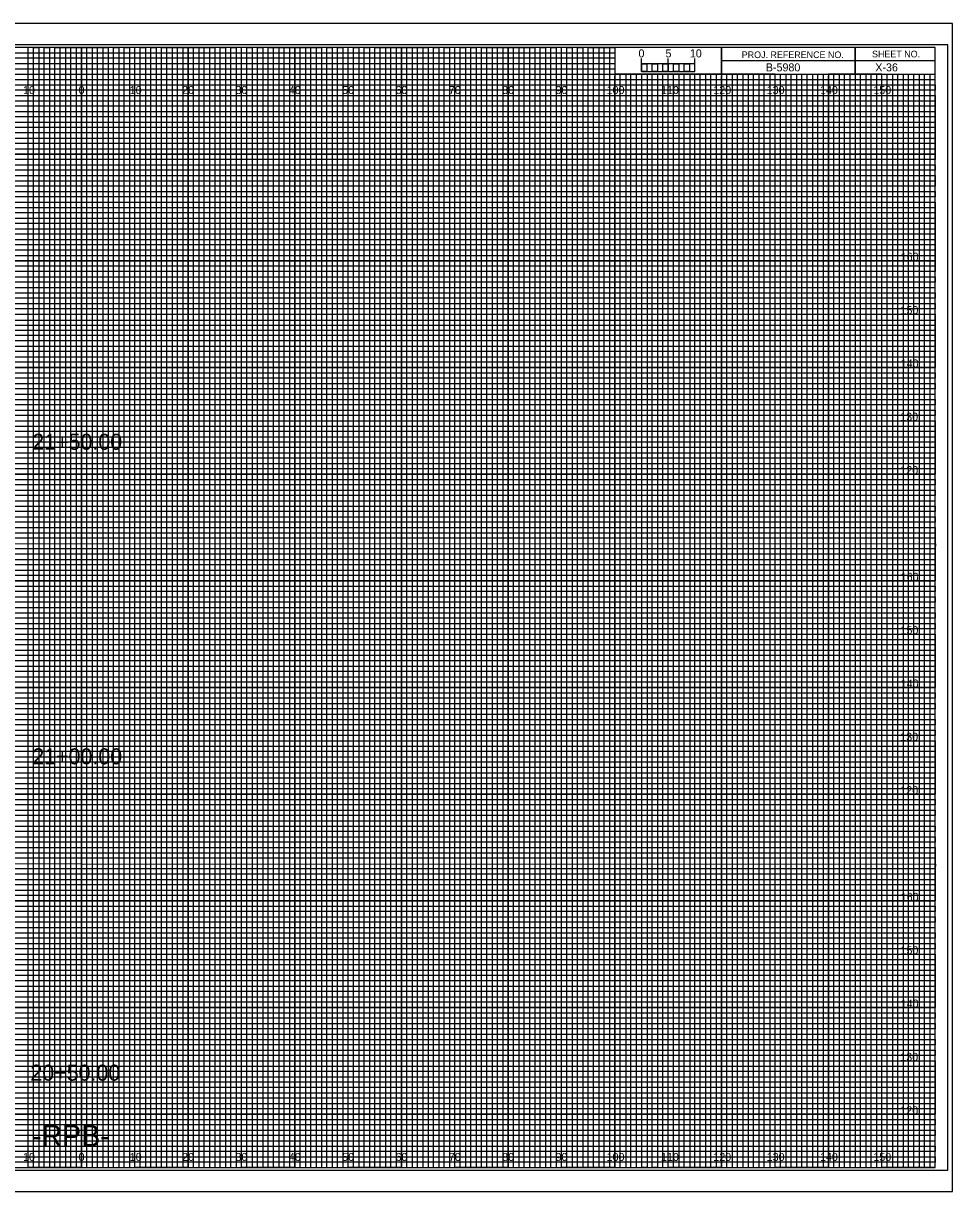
# Model space of a CAD drawing. Extents: x -13 to 323, y -5 to 1094.
# Drawn here: x 149.1 to 323.3, y 655.5 to 874.5 of the extents above; entities that cross this region are included whole.
import ezdxf

# ---------------------------------------------------------------- set-up
doc = ezdxf.new("R2010")
doc.units = 0
for name, color, linetype in [('Exist Cross Section Cell', 7, 'Continuous'), ('Exist XS Center Line Elevation Label', 7, 'Continuous'), ('Exist XS Ground Line', 7, 'Continuous'), ('Prop CMT Concrete Structures', 7, 'Continuous'), ('Prop CMT Guardrail Graphics', 7, 'Continuous'), ('Prop CMT Pvmt Course 1', 7, 'Continuous'), ('Prop CMT Pvmt Course 1 CG', 7, 'Continuous'), ('Prop CMT Pvmt Course 2', 7, 'Continuous'), ('Prop CMT Pvmt Course 3', 7, 'Continuous'), ('Prop CMT Pvmt Surface', 7, 'Continuous'), ('Prop CMT Pvmt Surface Shoulder', 7, 'Continuous'), ('Prop CMT Shld Paved Course 1', 7, 'Continuous'), ('Prop CMT Shld Paved Course 2', 7, 'Continuous'), ('Prop CMT Shld Paved Course 3', 7, 'Continuous'), ('Prop CMT Slope Grass', 7, 'Continuous'), ('Prop CMT Subgrade Earthwork', 7, 'Continuous'), ('Scratch_Level_1', 7, 'Continuous')]:
    doc.layers.add(name, color=color, linetype=linetype)

msp = doc.modelspace()

# ---------------------------------------------------------------- linework, layer by layer
at = {"layer": 'Exist XS Center Line Elevation Label'}
for points in [[(145, 660), (155, 660), (155, 870), (165, 870), (165, 660), (175, 660), (175, 870), (185, 870), (185, 660), (195, 660), (195, 870), (205, 870), (205, 660), (215, 660), (215, 870), (225, 870), (225, 660), (235, 660), (235, 870), (245, 870), (245, 660), (255, 660), (255, 870), (259.93, 870), (260, 870), (260, 865), (264.99, 865), (264.99, 660), (275, 660), (275, 865), (285, 865), (285, 660), (295, 660), (295, 865), (305, 865), (305, 660), (315, 660), (315, 865)], [(0, 865), (275, 865)], [(0, 845), (320, 845), (320, 855), (0, 855)], [(0, 825), (320, 825), (320, 835), (0, 835)], [(0, 805), (320, 805), (320, 815), (0, 815)], [(0, 785), (320, 785), (320, 795), (0, 795)], [(0, 765), (320, 765), (320, 775), (0, 775)], [(0, 745), (320, 745), (320, 755), (0, 755)], [(0, 725), (320, 725), (320, 735), (0, 735)], [(0, 705), (320, 705), (320, 715), (0, 715)], [(0, 685), (320, 685), (320, 695), (0, 695)], [(0, 665), (320, 665), (320, 675), (0, 675)]]:
    msp.add_lwpolyline(points, dxfattribs=at)
at = {"layer": 'Exist XS Ground Line'}
for p, q in [((150, 870), (140, 870)), ((150, 660), (150, 870)), ((170, 870), (160, 870)), ((160, 870), (160, 660)), ((170, 660), (170, 870)), ((190, 870), (180, 870)), ((180, 870), (180, 660)), ((190, 660), (190, 870)), ((210, 870), (200, 870)), ((200, 870), (200, 660)), ((210, 660), (210, 870)), ((230, 870), (220, 870)), ((220, 870), (220, 660)), ((230, 660), (230, 870)), ((250, 870), (240, 870)), ((240, 870), (240, 660)), ((250, 660), (250, 870)), ((260, 870), (260, 660)), ((270, 660), (270, 865)), ((290, 865), (280, 865)), ((280, 865), (280, 660)), ((290, 660), (290, 865)), ((310, 865), (300, 865)), ((300, 865), (300, 660)), ((310, 660), (310, 865)), ((160, 660), (150, 660)), ((180, 660), (170, 660)), ((200, 660), (190, 660)), ((220, 660), (210, 660)), ((240, 660), (230, 660)), ((260, 660), (250, 660)), ((280, 660), (270, 660)), ((300, 660), (290, 660)), ((320, 660), (310, 660)), ((320, 660), (320, 660))]:
    msp.add_line(p, q, dxfattribs=at)
for points in [[(0, 860), (320, 860), (320, 850), (0, 850)], [(0, 840), (320, 840), (320, 830), (0, 830)], [(0, 820), (320, 820), (320, 810), (0, 810)], [(0, 800), (320, 800), (320, 790), (0, 790)], [(0, 780), (320, 780), (320, 770), (0, 770)], [(0, 760), (320, 760), (320, 750), (0, 750)], [(0, 740), (320, 740), (320, 730), (0, 730)], [(0, 720), (320, 720), (320, 710), (0, 710)], [(0, 700), (320, 700), (320, 690), (0, 690)], [(0, 680), (320, 680), (320, 670), (0, 670)]]:
    msp.add_lwpolyline(points, dxfattribs=at)
at = {"layer": 'Prop CMT Pvmt Course 2'}
for p, q in [((265, 865.49), (265, 867.9)), ((265, 866.9), (265, 867.9)), ((270, 865.49), (270, 867.9)), ((275, 865.49), (275, 867.9)), ((275, 866.9), (275, 867.9))]:
    msp.add_line(p, q, dxfattribs=at)
for points in [[(275, 866.9), (265, 866.9), (265, 865.49), (275, 865.49)], [(265, 866.9), (266, 866.9), (266, 865.49), (265, 865.49)], [(267, 866.9), (268, 866.9), (268, 865.49), (267, 865.49)], [(269, 866.9), (270, 866.9), (270, 865.49), (269, 865.49)], [(271, 866.9), (272, 866.9), (272, 865.49), (271, 865.49)], [(273, 866.9), (274, 866.9), (274, 865.49), (273, 865.49)]]:
    msp.add_lwpolyline(points, close=True, dxfattribs=at)
at = {"layer": 'Prop CMT Pvmt Course 3'}
msp.add_lwpolyline([(-13.4, 655.5), (323.3, 655.5), (323.3, 874.5), (-13.4, 874.5)], close=True, dxfattribs=at)
at = {"layer": 'Prop CMT Pvmt Surface'}
for p, q in [((150, 660), (150, 870)), ((160, 660), (160, 870)), ((170, 660), (170, 870)), ((180, 660), (180, 870)), ((190, 660), (190, 870)), ((200, 660), (200, 870)), ((210, 660), (210, 870)), ((220, 660), (220, 870)), ((230, 660), (230, 870)), ((240, 660), (240, 870)), ((250, 660), (250, 870)), ((260, 660), (260, 864.69)), ((270, 660), (270, 864.69)), ((280, 660), (280, 864.69)), ((290, 660), (290, 864.69)), ((300, 660), (300, 864.69)), ((310, 660), (310, 864.69)), ((0, 860), (320, 860)), ((0, 850), (320, 850)), ((0, 840), (320, 840)), ((0, 830), (320, 830)), ((0, 820), (320, 820)), ((0, 810), (320, 810)), ((0, 800), (320, 800)), ((0, 790), (320, 790)), ((0, 780), (320, 780)), ((0, 770), (320, 770)), ((0, 760), (320, 760)), ((0, 750), (320, 750)), ((0, 740), (320, 740)), ((0, 730), (320, 730)), ((0, 720), (320, 720)), ((0, 710), (320, 710)), ((0, 700), (320, 700)), ((0, 690), (320, 690)), ((0, 680), (320, 680)), ((0, 670), (320, 670))]:
    msp.add_line(p, q, dxfattribs=at)
at = {"layer": 'Prop CMT Pvmt Surface Shoulder'}
for p, q in [((323.3, 874.5), (-13.4, 874.5)), ((-13.4, 655.5), (323.3, 655.5))]:
    msp.add_line(p, q, dxfattribs=at)
at = {"layer": 'Prop CMT Shld Paved Course 1'}
for p, q in [((0, 869), (260, 869)), ((260, 867.98), (0, 867.98)), ((260, 869), (260, 867.98)), ((0, 867), (260, 867)), ((260, 865.89), (0, 865.89)), ((260, 867), (260, 865.89)), ((0, 864), (320, 864))]:
    msp.add_line(p, q, dxfattribs=at)
for points in [[(0, 863), (270, 863), (320, 863), (320, 862), (0, 862)], [(0, 861), (320, 861), (320, 859), (0, 859)], [(0, 858), (320, 858), (320, 857), (0, 856.98)], [(0, 856), (320, 856), (320, 854), (0, 854)], [(0, 853), (320, 853), (320, 852), (0, 852)], [(0, 851), (320, 851), (320, 849), (0, 849)], [(0, 848), (320, 848), (320, 847), (0, 847)], [(0, 846), (320, 846), (320, 844), (0, 844)], [(0, 843), (320, 843), (320, 842), (0, 842)], [(0, 841), (320, 841), (320, 839), (0, 839)], [(0, 838), (320, 838), (320, 837), (0, 837)], [(0, 836), (320, 836), (320, 833.95), (320, 833), (320, 832), (0, 832)], [(0, 834), (320, 834), (320, 833), (0, 833)], [(0, 831), (320, 831), (320, 829), (0, 829.03)], [(0, 829.03), (320, 829), (320, 828), (0, 828)], [(0, 827), (320, 827), (320, 826), (0, 826)], [(0, 824), (320, 824), (320, 823), (0, 823)], [(0, 822), (320, 822), (320, 821), (0, 821)], [(-0.07, 818.89), (320, 818.89), (320, 817.88), (-0.07, 817.88)], [(0, 817), (320, 817), (320, 816), (0, 816)], [(0, 814), (320, 814), (320, 813), (0, 813)], [(0, 812), (320, 812), (320, 811), (0, 811)], [(0, 809), (320, 809), (320, 808), (0, 808)], [(0, 807), (320, 807), (320, 806), (0, 806)], [(0, 804), (320, 804), (320, 803), (0, 803)], [(0, 802), (320, 802), (320, 801), (0, 801)], [(0, 799), (320, 799), (319.99, 797.98), (0, 798)], [(0, 797), (320, 797), (320, 796), (0, 796)], [(0, 794), (320, 794), (320, 793), (0, 793)], [(0, 792), (320, 792), (320, 791), (0, 791)], [(0, 789), (320, 789), (320, 788), (0, 788)], [(0, 787), (320, 787), (320, 786), (0, 786)], [(0, 784), (320, 784), (320, 783), (0, 783)], [(0, 782), (320, 782), (320, 781), (0, 781)], [(0, 779), (320, 779), (320, 778), (0, 778)], [(0, 776.99), (320.07, 776.91), (320, 776), (0, 776)], [(0, 774), (320, 774), (320, 773), (0, 773)], [(0, 772), (320, 772), (320, 771), (0, 771)], [(0, 769), (320, 769), (320, 768), (0, 768)], [(0, 767), (320, 767), (320, 766), (0, 766)], [(0, 764), (320, 764), (320, 763), (0, 763)], [(0, 762), (320, 762), (320, 761), (0, 761)], [(0, 759), (320, 759), (320, 758), (0, 758)], [(0, 757), (320, 757), (320, 756), (0, 756)], [(0, 754), (320, 754), (320, 753), (0, 753)], [(0, 752), (320, 752), (320, 751), (0, 751)], [(0, 749), (320, 749), (320, 748), (0, 748)], [(0, 747), (320, 747), (320, 746), (0, 746)], [(0, 744), (320, 744), (320, 743), (0, 743)], [(0, 742), (320, 742), (320, 741), (0, 741)], [(0, 739), (320, 739), (319.99, 737.98), (0, 738)], [(0, 737), (320, 737), (320, 736), (0, 736)], [(0, 734), (320, 734), (320, 733), (0, 733)], [(0, 732), (320, 732), (320, 731), (0, 731)], [(0, 729), (320, 729), (320, 728), (0, 728)], [(0, 727), (320, 727), (320, 726), (0, 726)], [(0, 724), (320, 724), (320, 723), (0, 723)], [(0, 722), (320, 722), (320, 721), (0, 721)], [(0, 719), (320, 719), (320, 718), (0, 718)], [(0, 716.99), (320.07, 716.91), (320, 716), (0, 716)], [(0, 714), (320, 714), (320, 713), (0, 713)], [(0, 712), (320, 712), (320, 711), (0, 711)], [(0, 709), (320, 709), (320, 708), (0, 708)], [(0, 707), (320, 707), (320, 706), (0, 706)], [(0, 704), (320, 704), (320, 703), (0, 703)], [(0, 702), (320, 702), (320, 701), (0, 701)], [(0, 699), (320, 699), (320, 698), (0, 698)], [(0, 697), (320, 697), (320, 696), (0, 696)], [(0, 694), (320, 694), (320, 693), (0, 693)], [(0, 692), (320, 692), (320, 691), (0, 691)], [(0, 689), (320, 689), (320, 688), (0, 688)], [(0, 687), (320, 687), (320, 686), (0, 686)], [(0, 684), (320, 684), (320, 683), (0, 683)], [(0, 682), (320, 682), (320, 681), (0, 681)], [(0, 679), (320, 679), (320, 678), (0, 678)], [(0, 677), (320, 677), (320, 676), (0, 676)], [(0, 674), (320, 674), (320, 673), (0, 673)], [(0, 672), (320, 672), (320, 671), (0, 671)], [(0, 669), (320, 669), (320, 668), (0, 668)], [(0, 667), (320, 667), (320, 666), (0, 666)], [(0, 664), (320, 664), (320, 663), (0, 663)], [(0, 662), (320, 662), (320, 661), (0, 661)]]:
    msp.add_lwpolyline(points, dxfattribs=at)
at = {"layer": 'Prop CMT Shld Paved Course 2'}
for p, q in [((305, 870), (305, 865)), ((305, 865), (305, 870)), ((280, 867.5), (280, 865)), ((320, 867.49), (280, 867.49)), ((280, 865), (320, 865))]:
    msp.add_line(p, q, dxfattribs=at)
for points in [[(320, 870), (0, 870), (0, 660), (320, 660)], [(280, 870), (260, 870), (260, 865.03), (280, 865.03)], [(320, 870), (280, 870), (280, 865), (320, 865)]]:
    msp.add_lwpolyline(points, close=True, dxfattribs=at)
at = {"layer": 'Prop CMT Shld Paved Course 3'}
for p, q in [((267, 865), (266.01, 865)), ((266.01, 865), (266.01, 660)), ((267, 660), (267, 865)), ((269, 865), (268, 865)), ((268, 865), (268, 660)), ((269, 660), (269, 865)), ((266.01, 660), (265, 660)), ((268, 660), (267, 660))]:
    msp.add_line(p, q, dxfattribs=at)
for points in [[(150, 660), (151, 660), (151, 870), (152, 870), (152, 660)], [(152, 660), (153, 660), (153, 870), (154, 870), (154, 660)], [(155, 660), (156, 660), (156, 870), (157, 870), (157, 660)], [(157, 660), (158, 660), (158, 870), (159, 870), (159, 660)], [(160, 660), (161, 660), (161, 870), (162, 870), (162, 660)], [(162, 660), (163, 660), (163, 870), (164, 870), (164, 660)], [(165, 660), (166, 660), (166, 870), (167, 870), (167, 660)], [(167, 660), (168, 660), (168, 870), (169, 870), (169, 660)], [(170, 660), (171, 660), (171, 870), (172, 870), (172, 660)], [(172, 660), (173, 660), (173, 870), (174, 870), (174, 660)], [(175, 660), (176, 660), (176, 870), (177, 870), (177, 660)], [(177, 660), (178, 660), (178, 870), (179, 870), (179, 660)], [(180, 660), (181, 660), (181, 870), (182, 870), (182, 660)], [(182, 660), (183, 660), (183, 870), (184, 870), (184, 660)], [(185, 660), (186, 660), (186, 870), (187, 870), (187, 660)], [(187, 660), (188, 660), (188, 870), (189, 870), (189, 660)], [(190, 660), (191, 660), (191, 870), (192, 870), (192, 660)], [(192, 660), (193, 660), (193, 870), (194, 870), (194, 660)], [(195, 660), (196, 660), (196, 870), (197, 870), (197, 660)], [(197, 660), (198, 660), (198, 870), (199, 870), (199, 660)], [(200, 660), (201, 660), (201, 870), (202, 870), (202, 660)], [(202, 660), (203, 660), (203, 870), (204, 870), (204, 660)], [(205, 660), (206, 660), (206, 870), (207, 870), (207, 660)], [(207, 660), (208, 660), (208, 870), (209, 870), (209, 660)], [(210, 660), (211, 660), (211, 870), (212, 870), (212, 660)], [(212, 660), (213, 660), (213, 870), (214, 870), (214, 660)], [(215, 660), (216, 660), (216, 870), (217, 870), (217, 660)], [(217, 660), (218, 660), (218, 870), (219, 870), (219, 660)], [(220, 660), (221, 660), (221, 870), (222, 870), (222, 660)], [(222, 660), (223, 660), (223, 870), (224, 870), (224, 660)], [(225, 660), (226, 660), (226, 870), (227, 870), (227, 660)], [(227, 660), (228, 660), (228, 870), (229, 870), (229, 660)], [(230, 660), (231, 660), (231, 870), (232, 870), (232, 660)], [(232, 660), (233, 660), (233, 870), (234, 870), (234, 660)], [(235, 660), (236, 660), (236, 870), (237, 870), (237, 660)], [(237, 660), (238, 660), (238, 870), (239, 870), (239, 660)], [(240, 660), (241, 660), (241, 870), (242, 870), (242, 660)], [(242, 660), (243, 660), (243, 870), (244, 870), (244, 660)], [(245, 660), (246, 660), (246, 870), (247, 870), (247, 660)], [(247, 660), (248, 660), (248, 870), (249, 870), (249, 660)], [(250, 660), (251, 660), (251, 870), (252, 870), (252, 660)], [(252, 660), (253, 660), (253, 870), (254, 870), (254, 660)], [(255, 660), (256, 660), (256, 870), (257, 870), (257, 660)], [(257, 660), (258, 660), (258, 870), (259, 870), (259, 660)], [(260, 660), (261, 660), (261, 865), (262.02, 865), (262.02, 660)], [(262, 660), (263, 660), (263, 865), (263.99, 865), (263.99, 660)], [(270, 660), (270.98, 660), (270.98, 865), (272, 865), (272, 660)], [(272, 660), (273, 660), (273, 865), (274.05, 865), (274.05, 660)], [(275, 660), (276, 660), (276, 865), (277, 865), (277, 660)], [(277, 660), (278, 660), (278, 865), (279, 865), (279, 660)], [(280, 660), (281, 660), (281, 865), (282, 865), (282, 660)], [(282, 660), (283, 660), (283, 865), (284, 865), (284, 660)], [(285, 660), (286, 660), (286, 865), (287, 865), (287, 660)], [(287, 660), (288, 660), (288, 865), (289, 865), (289, 660)], [(290, 660), (291, 660), (291, 865), (292, 865), (292, 660)], [(292, 660), (293, 660), (293, 865), (294, 865), (294, 660)], [(295, 660), (296, 660), (296, 865), (297, 865), (297, 660)], [(297, 660), (298, 660), (298, 865), (299, 865), (299, 660)], [(300, 660), (301, 660), (301, 865), (302, 865), (302, 660)], [(302, 660), (303, 660), (303, 865), (304, 865), (304, 660)], [(305, 660), (306, 660), (306, 865), (307, 865), (307, 660)], [(307, 660), (308, 660), (308, 865), (309, 865), (309, 660)], [(310, 660), (311, 660), (311, 865), (312, 865), (312, 660)], [(312, 660), (313, 660), (313, 865), (314, 865), (314, 660)], [(315, 660), (316, 660), (316, 865), (317, 865), (317, 660)], [(317, 660), (318, 660), (318, 865), (319, 865), (319, 660)]]:
    msp.add_lwpolyline(points, dxfattribs=at)
at = {"layer": 'Prop CMT Subgrade Earthwork'}
msp.add_lwpolyline([(-10.8, 659.5), (322.4, 659.5), (322.4, 870.5), (-10.8, 870.5)], close=True, dxfattribs=at)

# ---------------------------------------------------------------- texts
at = {"layer": 'Exist Cross Section Cell'}
for s, p in [('10', (149.04, 861.25)), ('0', (159.45, 861.25)), ('0', (159.45, 861.25)), ('10', (169.04, 861.25)), ('20', (178.86, 861.25)), ('30', (188.86, 861.25)), ('40', (198.86, 861.25)), ('50', (208.86, 861.25)), ('60', (218.86, 861.25)), ('70', (228.86, 861.25)), ('80', (238.86, 861.25)), ('90', (248.86, 861.25)), ('100', (258.44, 861.25)), ('110', (268.62, 861.25)), ('120', (278.44, 861.25)), ('130', (288.44, 861.25)), ('140', (298.44, 861.25)), ('150', (308.44, 861.25)), ('10', (149.04, 661.25)), ('0', (159.45, 661.25)), ('0', (159.45, 661.25)), ('10', (169.04, 661.25)), ('20', (178.86, 661.25)), ('30', (188.86, 661.25)), ('40', (198.86, 661.25)), ('50', (208.86, 661.25)), ('60', (218.86, 661.25)), ('70', (228.86, 661.25)), ('80', (238.86, 661.25)), ('90', (248.86, 661.25)), ('100', (258.44, 661.25)), ('110', (268.62, 661.25)), ('120', (278.44, 661.25)), ('130', (288.44, 661.25)), ('140', (298.44, 661.25)), ('150', (308.44, 661.25))]:
    msp.add_text(s, height=1.5, dxfattribs=at).set_placement(p)
at = {"layer": 'Prop CMT Concrete Structures'}
msp.add_text('-RPB-', height=4, dxfattribs=at).set_placement((150.72, 664))
at = {"layer": 'Prop CMT Guardrail Graphics'}
msp.add_text('X-36', height=1.5, dxfattribs=at).set_placement((308.8, 865.5))
at = {"layer": 'Prop CMT Pvmt Course 1'}
for s, p in [('160', (313.57, 830)), ('150', (313.52, 820)), ('140', (313.57, 810)), ('130', (313.49, 800)), ('120', (313.5, 790)), ('160', (313.57, 770)), ('150', (313.52, 760)), ('140', (313.57, 750)), ('130', (313.49, 740)), ('120', (313.5, 730)), ('160', (313.57, 710)), ('150', (313.52, 700)), ('140', (313.57, 690)), ('130', (313.49, 680)), ('120', (313.5, 670))]:
    msp.add_text(s, height=1.5, dxfattribs=at).set_placement(p)
at = {"layer": 'Prop CMT Pvmt Course 1 CG'}
for s, p in [('5', (269.47, 868.12)), ('10', (274.04, 868.12))]:
    msp.add_text(s, height=1.5, dxfattribs=at).set_placement(p)
at = {"layer": 'Prop CMT Pvmt Course 2'}
msp.add_text('0', height=1.5, dxfattribs=at).set_placement((264.41, 868.12))
at = {"layer": 'Prop CMT Shld Paved Course 2'}
for s, p in [('PROJ. REFERENCE NO.', (283.77, 867.99)), ('SHEET NO.', (308.19, 868.12))]:
    msp.add_text(s, height=1.25, dxfattribs=at).set_placement(p)
at = {"layer": 'Prop CMT Slope Grass'}
for s, p in [('21+50.00', (150.77, 794.57)), ('21+00.00', (150.77, 735.6)), ('20+50.00', (150.41, 676.3))]:
    msp.add_text(s, height=3, dxfattribs=at).set_placement(p)
at = {"layer": 'Scratch_Level_1'}
msp.add_text('B-5980', height=1.5, dxfattribs=at).set_placement((288.28, 865.5))

doc.saveas('drawing.dxf')
